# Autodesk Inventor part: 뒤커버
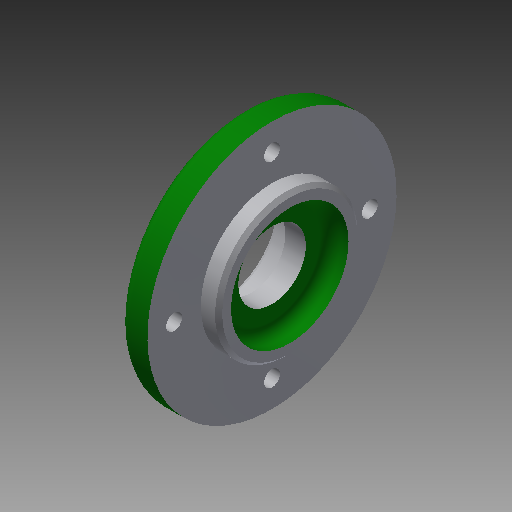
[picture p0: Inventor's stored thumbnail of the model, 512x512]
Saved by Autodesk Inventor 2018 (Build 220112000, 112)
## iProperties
Created: 2019-01
Part Number: 뒤커버
Material: 알루미늄 6061
Document SubType Name: Modeling
Designer: mduedu
Density: 1 g/cm^3
Appearance: 알루미늄 - 평지
Author: mduedu
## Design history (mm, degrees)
sketch "스케치1"
  geometry: L1 (0, 0)-(6, 0); L2 (6, 0)-(6, 20); L3 (6, 20)-(0, 20); L4 (0, 20)-(0, 0); L5 (6, 0)-(14, 0); L6 (14, 0)-(14, 35); L7 (14, 35)-(6, 35); L8 (6, 35)-(6, 0); L9 (14, 0)-(19, 0); L10 (19, 0)-(19, 20); L11 (19, 20)-(14, 20); L12 (14, 20)-(14, 0)
  constraints: 24 end point, 6 parallel, 3 horizontal, 3 perpendicular
  dimensions: "d6" = 70 diameter of L7 L5; "d8" = 40 diameter of L3 L1; "d9" = 40 diameter of L11 L9; "d10" = 5 distance of L10.end L11.end; "d11" = 6 distance of L2.end L3.end; "d12" = 19 distance between parallel lines of L4 L10; "d13" = 8 distance of L6.end L7.end (derived)
revolve "회전1" sketch "스케치1" stored, may be unused: angle "d5" = 90 deg
sketch "스케치2" dims "d14" = 55
  geometry: 7 further points
  constraints: 2 coincident, 2 vertical alignment, 7 other
  dimensions: "d17" = 360 deg dimension on point (0, 0) point (0, 27.5) (derived)
sketch "스케치3"
  geometry: 4 further points
  constraints: 4 other
hole "구멍1" sketch "스케치3" at (0, 27.5), (-27.5, 0), (27.5, 0), (0, -27.5) diameter "d19" = 4.5; stored, may be unused: countersink angle "d23" = 90 deg, drill point angle "d25" = 0 deg; dims "d20" = 6, "d21" = 8, "d22" = 4.6, "d24" = 8
fillet "모깎기1" dims "d26" = 3
sketch "스케치4"
  geometry: C1 r 9.5 at (0, 0); 1 further point
  constraints: 1 centre point, 1 coincident
  dimensions: "d27" = 19 diameter of C1
extrude "돌출1" cut sketch "스케치4" extent not by distance; stored distance "d28" = 10; taper "d29" = 0 deg
sketch "스케치5"
  geometry: C1 r 15 at (0, 0); 1 further point
  constraints: 1 centre point, 1 coincident
  dimensions: "d31" = 30 diameter of C1
extrude "돌출2" cut sketch "스케치5" distance "d32" = 8.3; taper "d33" = 0 deg
chamfer "모따기1" distance "d34" = 0.8; stored, may be unused: second distance "d35" = 2, angle "d36" = 30 deg
fillet "모깎기2" dims "d37" = 3
fillet "모깎기3" dims "d38" = 0.5
sketch "스케치6"
  geometry: C1 r 16.5 at (0, 0); 1 further point
  constraints: 1 centre point, 1 coincident
  dimensions: "d39" = 33 diameter of C1
extrude "돌출3" cut sketch "스케치6" distance "d40" = 5; taper "d41" = 0 deg
fillet "모깎기4" dims "d42" = 3
chamfer "모따기2" distance "d43" = 1; stored, may be unused: second distance "d44" = 2, angle "d45" = 30 deg
node "솔리드1"
